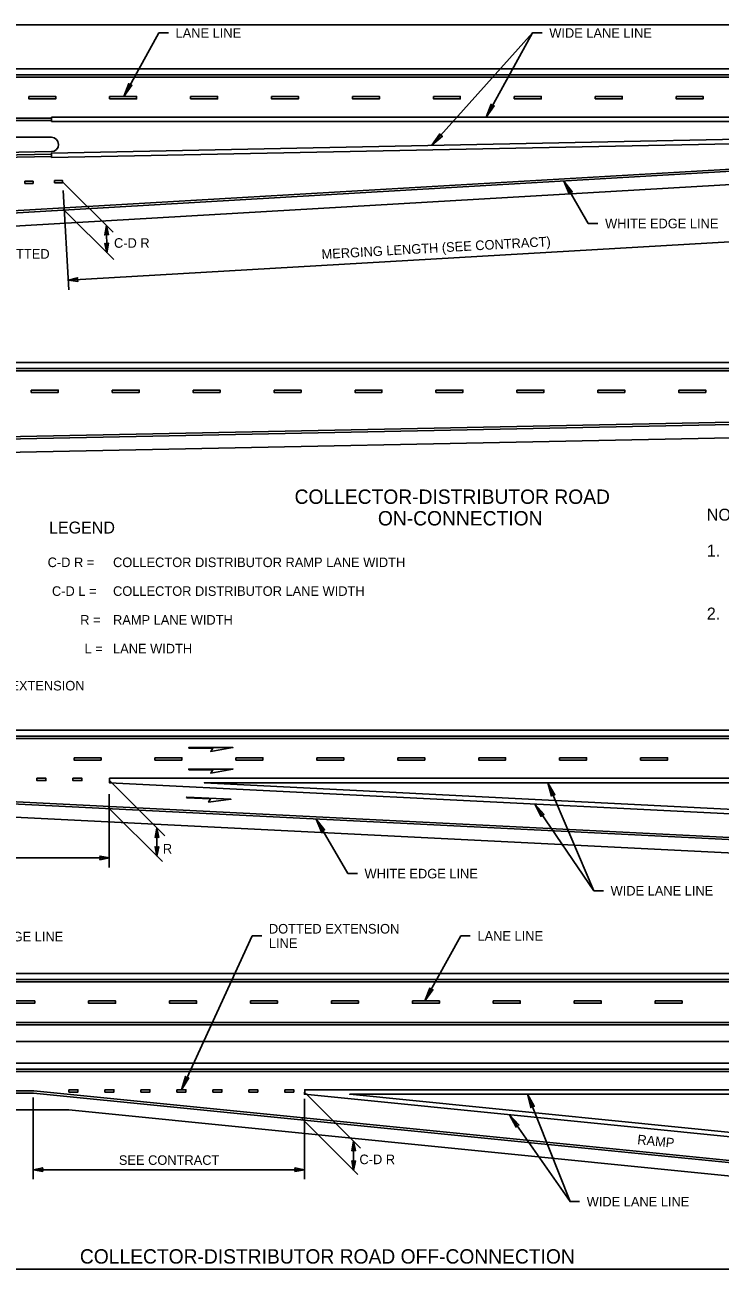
# Model space of a CAD drawing. Extents: x 99862 to 103151, y 100000 to 102076.
# Drawn here: x 100803 to 101963, y 100000 to 102076 of the extents above; entities that cross this region are included whole.
import ezdxf

# ---------------------------------------------------------------- set-up
doc = ezdxf.new("R2010")
doc.units = 0
for name, color, linetype in [('Level 1', 7, 'Continuous'), ('Level 15', 7, 'Continuous'), ('Level 2', 7, 'Continuous'), ('Level 20', 7, 'Continuous'), ('Level 3', 7, 'Continuous'), ('Level 4', 7, 'Continuous'), ('Level 5', 7, 'Continuous'), ('Level 7', 7, 'Continuous')]:
    doc.layers.add(name, color=color, linetype=linetype)

msp = doc.modelspace()

# ---------------------------------------------------------------- linework, layer by layer
at = {"layer": 'Level 1'}
msp.add_lwpolyline([(99862, 99999.5), (103151, 99999.5), (103151, 102075.5), (99862, 102075.5)], close=True, dxfattribs=at)
at = {"layer": 'Level 15'}
for p, q in [((100968.3, 101956.1), (101026.7, 102062)), ((101026.7, 102062), (101042.7, 102062)), ((101026.7, 102062), (101042.7, 102062)), ((101650.1, 102062), (101482.3, 101874.6)), ((101650.1, 102062), (101482.3, 101874.6)), ((101572.7, 101921.7), (101650.1, 102062)), ((101572.7, 101921.7), (101650.1, 102062)), ((101650.1, 102062), (101666.1, 102062)), ((101650.1, 102062), (101666.1, 102062)), ((100866.3, 101813.9), (100950.6, 101729.6)), ((101702.3, 101815), (101743.2, 101744.1)), ((101702.3, 101815), (101743.2, 101744.1)), ((100867.1, 101799.4), (100876.7, 101633.7)), ((100867.2, 101768.3), (100951.5, 101684.1)), ((100940.2, 101695.4), (100939.3, 101740.9)), ((100940.2, 101695.4), (100939.3, 101740.9)), ((101743.2, 101744.1), (101759.2, 101744.1)), ((101743.2, 101744.1), (101759.2, 101744.1)), ((100944.4, 100814.7), (101036.5, 100722.7)), ((100944.4, 100814.7), (101036.5, 100722.7)), ((101675.7, 100810.9), (101752.4, 100630.8)), ((100944.1, 100669.6), (100944.1, 100792.2)), ((100942.3, 100769.9), (101032.7, 100679.4)), ((100942.3, 100769.9), (101032.7, 100679.4)), ((101654.1, 100775.5), (101752.4, 100630.8)), ((101341.9, 100659.4), (101289.3, 100750.5)), ((101341.9, 100659.4), (101289.3, 100750.5)), ((101023.6, 100688.5), (101023.6, 100735.5)), ((100944.2, 100685.6), (100043.2, 100685.6)), ((101341.9, 100659.4), (101357.9, 100659.4)), ((101341.9, 100659.4), (101357.9, 100659.4)), ((101752.4, 100630.8), (101768.4, 100630.8)), ((101752.4, 100630.8), (101768.4, 100630.8)), ((101064.4, 100298.9), (101182.4, 100555.4)), ((101182.4, 100555.4), (101198.4, 100555.4)), ((101182.4, 100555.4), (101198.4, 100555.4)), ((101470.5, 100447), (101530.3, 100555.4)), ((101470.5, 100447), (101530.3, 100555.4)), ((101530.3, 100555.4), (101546.3, 100555.4)), ((101269.9, 100294.7), (101363, 100201.5)), ((100817.4, 100149.4), (100817.4, 100285.7)), ((101269.5, 100149.4), (101269.5, 100283.5)), ((101641.7, 100291.3), (101712.8, 100112.1)), ((101265.4, 100250.6), (101358.8, 100157.2)), ((101612, 100257.1), (101712.8, 100112.1)), ((101351.7, 100212.8), (101351.7, 100177.1)), ((101351.7, 100212.8), (101351.7, 100164.3)), ((101269.5, 100165.4), (100817.5, 100165.4)), ((101712.5, 100112.1), (101728.5, 100112.1)), ((101712.5, 100112.1), (101728.5, 100112.1))]:
    msp.add_line(p, q, dxfattribs=at)
for points in [[(100968.3, 101956.1), (100976.7, 101977.5), (100978.8, 101975.2), (100981.9, 101974.7)], [(100968.3, 101956.1), (100976.7, 101977.5), (100978.8, 101975.2), (100981.9, 101974.7)], [(101572.7, 101921.7), (101581.1, 101943.2), (101583.2, 101940.8), (101586.4, 101940.3)], [(101572.7, 101921.7), (101581.1, 101943.2), (101583.2, 101940.8), (101586.4, 101940.3)], [(101482.3, 101874.6), (101495.3, 101893.6), (101496.8, 101890.8), (101499.8, 101889.6)], [(101482.3, 101874.6), (101495.3, 101893.6), (101496.8, 101890.8), (101499.8, 101889.6)], [(101702.3, 101815), (101716.3, 101796.7), (101713.1, 101796.1), (101711.1, 101793.7)], [(101702.3, 101815), (101716.3, 101796.7), (101713.1, 101796.1), (101711.1, 101793.7)], [(100939.3, 101740.9), (100942.7, 101725.3), (100939.6, 101725.9), (100936.5, 101725.2)], [(100939.3, 101740.9), (100942.7, 101725.3), (100939.6, 101725.9), (100936.5, 101725.2)], [(100940.2, 101695.4), (100942.9, 101711.2), (100939.9, 101710.4), (100936.8, 101711)], [(100940.2, 101695.4), (100942.9, 101711.2), (100939.9, 101710.4), (100936.8, 101711)], [(100875.8, 101649.7), (100891.3, 101653.7), (100890.8, 101650.6), (100891.7, 101647.5)], [(100875.8, 101649.7), (100891.3, 101653.7), (100890.8, 101650.6), (100891.7, 101647.5)], [(101675.7, 100810.9), (101687.4, 100791.1), (101684.2, 100790.9), (101681.9, 100788.8)], [(101654.1, 100775.5), (101669.4, 100758.2), (101666.4, 100757.4), (101664.5, 100754.9)], [(101289.3, 100750.5), (101298.1, 100729.3), (101300.2, 100731.7), (101303.3, 100732.3)], [(101289.3, 100750.5), (101298.1, 100729.3), (101300.2, 100731.7), (101303.3, 100732.3)], [(101023.6, 100735.5), (101026.7, 100719.8), (101023.6, 100720.5), (101020.5, 100719.8)], [(100944.2, 100685.6), (100928.4, 100682.5), (100929.2, 100685.6), (100928.4, 100688.7)], [(101023.6, 100688.5), (101026.7, 100704.3), (101023.6, 100703.5), (101020.5, 100704.2)], [(101470.5, 100447), (101478.9, 100468.5), (101481, 100466.1), (101484.1, 100465.6)], [(101470.5, 100447), (101478.9, 100468.5), (101481, 100466.1), (101484.1, 100465.6)], [(101064.4, 100298.9), (101071.2, 100320.9), (101073.5, 100318.7), (101076.6, 100318.4)], [(101641.7, 100291.3), (101647.3, 100269), (101649.7, 100271), (101652.9, 100271.2)], [(101641.7, 100291.3), (101647.3, 100269), (101649.7, 100271), (101652.9, 100271.2)], [(101612, 100257.1), (101622.6, 100236.6), (101624.4, 100239.2), (101627.5, 100240)], [(101612, 100257.1), (101622.6, 100236.6), (101624.4, 100239.2), (101627.5, 100240)], [(101351.7, 100212.8), (101354.8, 100197.1), (101351.7, 100197.8), (101348.6, 100197.1)], [(100817.5, 100165.4), (100833.2, 100162.4), (100832.4, 100165.4), (100833.2, 100168.5)], [(100817.5, 100165.4), (100833.2, 100162.4), (100832.4, 100165.4), (100833.2, 100168.5)], [(101269.5, 100165.4), (101253.8, 100162.4), (101254.5, 100165.4), (101253.8, 100168.5)], [(101269.5, 100165.4), (101253.8, 100162.4), (101254.5, 100165.4), (101253.8, 100168.5)], [(101351.7, 100164.3), (101354.8, 100180), (101351.7, 100179.3), (101348.6, 100180)]]:
    msp.add_lwpolyline(points, close=True, dxfattribs=at)
msp.add_lwpolyline([(102055.8, 101718.2), (100875.8, 101649.7)], dxfattribs=at)
at = {"layer": 'Level 2'}
for p, q in [((103122.6, 102002), (99944, 102002)), ((99944, 101888), (100847.5, 101888)), ((100476.9, 101721.6), (102047.6, 101812.9)), ((99911.9, 101512.1), (103093.2, 101512.1)), ((99944, 100898.7), (102630.3, 100898.7)), ((100224.7, 100493), (102409.4, 100493)), ((102409.4, 100379), (100224.7, 100379)), ((100224.7, 100343), (102409.4, 100343))]:
    msp.add_line(p, q, dxfattribs=at)
for points in [[(100847.7, 101864), (100247.6, 101852), (99944, 101852)], [(103091.7, 101403.9), (102836.7, 101403.9), (99911.9, 101344.9)], [(102630.3, 100670.7), (102442.8, 100670.7), (100162.8, 100784.7), (99944, 100784.7)], [(102630.3, 100670.7), (102442.8, 100670.7), (100162.8, 100784.7), (99944, 100784.7)], [(100224.7, 100265), (100876.6, 100265), (102275.7, 100125.1)]]:
    msp.add_lwpolyline(points, dxfattribs=at)
msp.add_arc((100847.5, 101876), 12, 271.1458, 90, dxfattribs=at)
at = {"layer": 'Level 3'}
for p, q in [((103122.6, 101991.9), (99944, 101991.9)), ((103122.6, 101991.9), (99944, 101991.9)), ((99944, 101988.1), (103122.6, 101988.1)), ((100847.9, 101914.2), (100847.9, 101921.7)), ((100847.9, 101914.2), (100847.9, 101921.7)), ((100847.9, 101921.7), (102922.5, 101921.7)), ((100847.9, 101921.7), (102922.5, 101921.7)), ((100847.9, 101914.2), (102922.5, 101914.2)), ((100847.9, 101914.2), (102922.5, 101914.2)), ((99911.9, 101501.9), (103093.2, 101501.9)), ((103093.2, 101498.2), (99911.9, 101498.2)), ((102630.4, 100888.6), (99944, 100888.6)), ((99944, 100884.8), (102630.4, 100884.8)), ((100224.7, 100482.9), (102409.4, 100482.9)), ((102409.4, 100479.1), (100224.7, 100479.1)), ((100224.7, 100332.9), (102409.4, 100332.9)), ((102409.4, 100329.2), (100224.7, 100329.2))]:
    msp.add_line(p, q, dxfattribs=at)
for points in [[(100847.9, 101854.2), (100847.8, 101861.7), (102922.5, 101903.7), (102922.7, 101896.2)], [(100847.9, 101854.2), (100847.8, 101861.7), (102922.5, 101903.7), (102922.7, 101896.2)], [(102504.5, 100810.9), (102504.5, 100818.4), (100944.5, 100818.4), (100944.3, 100811), (102504.3, 100733), (102504.7, 100740.4), (101102.5, 100810.9)], [(102109, 100214.9), (102108.2, 100207.4), (101269.7, 100291.3), (101270.1, 100298.8), (102111.6, 100298.8), (102111.6, 100291.3), (101345.3, 100291.3)]]:
    msp.add_lwpolyline(points, close=True, dxfattribs=at)
msp.add_lwpolyline([(99944, 101844.1), (100247.6, 101844.1), (100847.9, 101856.1), (100847.8, 101859.9), (100247.5, 101847.9), (99944, 101847.9)], dxfattribs=at)
at = {"layer": 'Level 4'}
for p, q in [((100847.9, 101919.9), (99944, 101919.9)), ((99944, 101916.1), (100847.9, 101916.1)), ((100224.7, 100410.9), (102409.4, 100410.9)), ((102409.4, 100407.2), (100224.7, 100407.2))]:
    msp.add_line(p, q, dxfattribs=at)
for points in [[(100809.7, 101956.1), (100854.7, 101956.1), (100854.7, 101952.1), (100809.7, 101952.2)], [(100944.7, 101956.1), (100989.7, 101956.1), (100989.7, 101952.1), (100944.7, 101952.2)], [(101079.7, 101956.1), (101124.7, 101956.1), (101124.7, 101952.1), (101079.7, 101952.2)], [(101214.7, 101956.1), (101259.7, 101956.1), (101259.7, 101952.1), (101214.7, 101952.2)], [(101214.7, 101956.1), (101259.7, 101956.1), (101259.7, 101952.1), (101214.7, 101952.2)], [(101349.7, 101956.1), (101394.7, 101956.1), (101394.7, 101952.1), (101349.7, 101952.2)], [(101349.7, 101956.1), (101394.7, 101956.1), (101394.7, 101952.1), (101349.7, 101952.2)], [(101484.7, 101956.1), (101529.7, 101956.1), (101529.7, 101952.1), (101484.7, 101952.2)], [(101484.7, 101956.1), (101529.7, 101956.1), (101529.7, 101952.1), (101484.7, 101952.2)], [(101619.7, 101956.1), (101664.7, 101956.1), (101664.7, 101952.1), (101619.7, 101952.2)], [(101754.7, 101956.1), (101799.7, 101956.1), (101799.7, 101952.1), (101754.7, 101952.2)], [(101889.7, 101956.1), (101934.7, 101956.1), (101934.7, 101952.1), (101889.7, 101952.2)], [(100803.4, 101810.9), (100816.9, 101810.9), (100816.9, 101814.7), (100803.4, 101814.7)], [(100803.4, 101810.9), (100816.9, 101810.9), (100816.9, 101814.7), (100803.4, 101814.7)], [(100852.8, 101812), (100866.3, 101812), (100866.3, 101815.7), (100852.8, 101815.7)], [(100852.8, 101812), (100866.3, 101812), (100866.3, 101815.7), (100852.8, 101815.7)], [(100814, 101466.2), (100859, 101466.2), (100859, 101462.2), (100814, 101462.2)], [(100949, 101466.2), (100994, 101466.2), (100994, 101462.2), (100949, 101462.2)], [(101084, 101466.2), (101129, 101466.2), (101129, 101462.2), (101084, 101462.2)], [(101219, 101466.2), (101264, 101466.2), (101264, 101462.2), (101219, 101462.2)], [(101354, 101466.2), (101399, 101466.2), (101399, 101462.2), (101354, 101462.2)], [(101489, 101466.2), (101534, 101466.2), (101534, 101462.2), (101489, 101462.2)], [(101624, 101466.2), (101669, 101466.2), (101669, 101462.2), (101624, 101462.2)], [(101759, 101466.2), (101804, 101466.2), (101804, 101462.2), (101759, 101462.2)], [(101894, 101466.2), (101939, 101466.2), (101939, 101462.2), (101894, 101462.2)], [(100885.3, 100852.7), (100930.3, 100852.7), (100930.3, 100848.7), (100885.3, 100848.7)], [(101020.3, 100852.7), (101065.3, 100852.7), (101065.3, 100848.7), (101020.3, 100848.7)], [(101020.3, 100852.7), (101065.3, 100852.7), (101065.3, 100848.7), (101020.3, 100848.7)], [(101155.3, 100852.7), (101200.3, 100852.7), (101200.3, 100848.7), (101155.3, 100848.7)], [(101290.3, 100852.7), (101335.3, 100852.7), (101335.3, 100848.7), (101290.3, 100848.7)], [(101425.3, 100852.7), (101470.3, 100852.7), (101470.3, 100848.7), (101425.3, 100848.7)], [(101560.3, 100852.7), (101605.3, 100852.7), (101605.3, 100848.7), (101560.3, 100848.7)], [(101695.3, 100852.7), (101740.3, 100852.7), (101740.3, 100848.7), (101695.3, 100848.7)], [(101830.3, 100852.7), (101875.3, 100852.7), (101875.3, 100848.7), (101830.3, 100848.7)], [(101830.3, 100852.7), (101875.3, 100852.7), (101875.3, 100848.7), (101830.3, 100848.7)], [(100823.4, 100818.6), (100838.4, 100818.6), (100838.4, 100814.6), (100823.4, 100814.6)], [(100823.4, 100818.6), (100838.4, 100818.6), (100838.4, 100814.6), (100823.4, 100814.6)], [(100883.4, 100818.6), (100898.4, 100818.6), (100898.4, 100814.6), (100883.4, 100814.6)], [(100883.4, 100818.6), (100898.4, 100818.6), (100898.4, 100814.6), (100883.4, 100814.6)], [(100774.7, 100447), (100819.7, 100447), (100819.7, 100443), (100774.7, 100443)], [(100774.7, 100447), (100819.7, 100447), (100819.7, 100443), (100774.7, 100443)], [(100909.7, 100447), (100954.7, 100447), (100954.7, 100443), (100909.7, 100443)], [(100909.7, 100447), (100954.7, 100447), (100954.7, 100443), (100909.7, 100443)], [(101044.7, 100447), (101089.7, 100447), (101089.7, 100443), (101044.7, 100443)], [(101044.7, 100447), (101089.7, 100447), (101089.7, 100443), (101044.7, 100443)], [(101179.7, 100447), (101224.7, 100447), (101224.7, 100443), (101179.7, 100443)], [(101179.7, 100447), (101224.7, 100447), (101224.7, 100443), (101179.7, 100443)], [(101314.7, 100447), (101359.7, 100447), (101359.7, 100443), (101314.7, 100443)], [(101314.7, 100447), (101359.7, 100447), (101359.7, 100443), (101314.7, 100443)], [(101449.7, 100447), (101494.7, 100447), (101494.7, 100443), (101449.7, 100443)], [(101449.7, 100447), (101494.7, 100447), (101494.7, 100443), (101449.7, 100443)], [(101584.7, 100447), (101629.7, 100447), (101629.7, 100443), (101584.7, 100443)], [(101584.7, 100447), (101629.7, 100447), (101629.7, 100443), (101584.7, 100443)], [(101719.7, 100447), (101764.7, 100447), (101764.7, 100443), (101719.7, 100443)], [(101719.7, 100447), (101764.7, 100447), (101764.7, 100443), (101719.7, 100443)], [(101854.7, 100447), (101899.7, 100447), (101899.7, 100443), (101854.7, 100443)], [(101854.7, 100447), (101899.7, 100447), (101899.7, 100443), (101854.7, 100443)], [(100876.9, 100298.9), (100891.9, 100298.9), (100891.9, 100294.9), (100876.9, 100294.9)], [(100936.9, 100298.9), (100951.9, 100298.9), (100951.9, 100294.9), (100936.9, 100294.9)], [(100996.9, 100298.9), (101011.9, 100298.9), (101011.9, 100294.9), (100996.9, 100294.9)], [(101056.9, 100298.9), (101071.9, 100298.9), (101071.9, 100294.9), (101056.9, 100294.9)], [(101116.9, 100298.9), (101131.9, 100298.9), (101131.9, 100294.9), (101116.9, 100294.9)], [(101176.9, 100298.9), (101191.9, 100298.9), (101191.9, 100294.9), (101176.9, 100294.9)], [(101236.9, 100298.9), (101251.9, 100298.9), (101251.9, 100294.9), (101236.9, 100294.9)]]:
    msp.add_lwpolyline(points, close=True, dxfattribs=at)
for points in [[(100475.1, 101747.4), (102048.8, 101838.9), (103122.6, 101860.8)], [(103122.6, 101857.1), (102049, 101835.1), (100475.5, 101743.7)], [(103093.2, 101429.9), (102838.2, 101429.9), (99911.9, 101370.9)], [(99944, 100816.6), (100043.4, 100816.6), (102323.5, 100702.6), (102630.3, 100702.6)], [(102630.3, 100698.8), (102323.3, 100698.8), (100043.4, 100812.8), (99944, 100812.8)], [(100224.7, 100296.9), (100818, 100296.9), (102278.3, 100150.9)], [(102277.9, 100147.1), (100817.6, 100293.2), (100224.7, 100293.2)]]:
    msp.add_lwpolyline(points, dxfattribs=at)
at = {"layer": 'Level 5'}
for points in [[(101076.6, 100868.7), (101116.7, 100868.7), (101113.5, 100863.3), (101150.4, 100869.8), (101076.6, 100869.8)], [(101076.6, 100832.6), (101116.7, 100832.6), (101113.5, 100827.2), (101150.4, 100833.7), (101076.6, 100833.7)], [(101073.1, 100786.1), (101113.2, 100784.1), (101109.7, 100778.8), (101146.9, 100783.5), (101073.2, 100787.1)]]:
    msp.add_lwpolyline(points, close=True, dxfattribs=at)
at = {"layer": 'Level 7'}
msp.add_lwpolyline([(99911.9, 101367.2), (102838.2, 101426.2), (103093.2, 101426.2)], dxfattribs=at)

# ---------------------------------------------------------------- texts
at = {"layer": 'Level 20'}
for s, height, p in [('LANE LINE', 16, (101054.7, 102054)), ('WIDE LANE LINE', 16, (101678.1, 102054)), ('WHITE EDGE LINE', 16, (101771.2, 101736.1)), ('C-D R', 16, (100952, 101703.6)), ('C-D R', 16, (100952, 101703.6)), ('WIDE DOTTED', 16, (100694.8, 101685.4)), ('COLLECTOR-DISTRIBUTOR ROAD', 24, (101253.2, 101276.3)), ('NOTES', 20, (101940.9, 101248.3)), ('LEGEND', 20, (100843.6, 101226.8)), ('ON-CONNECTION', 24, (101392.2, 101240.3)), ('1.', 20, (101940.9, 101188.3)), ('1.', 20, (101940.9, 101188.3)), ('C-D R =', 16, (100841.3, 101170.8)), ('C-D R =', 16, (100841.3, 101170.8)), ('COLLECTOR DISTRIBUTOR RAMP LANE WIDTH', 16, (100950.4, 101170.8)), ('C-D L =', 16, (100848.5, 101122.8)), ('C-D L =', 16, (100848.5, 101122.8)), ('COLLECTOR DISTRIBUTOR LANE WIDTH', 16, (100950.4, 101122.8)), ('2.', 20, (101940.9, 101083.3)), ('2.', 20, (101940.9, 101083.3)), ('R =', 16, (100895.6, 101074.8)), ('R =', 16, (100895.6, 101074.8)), ('RAMP LANE WIDTH', 16, (100950.4, 101074.8)), ('L =', 16, (100902.9, 101026.8)), ('L =', 16, (100902.9, 101026.8)), ('LANE WIDTH', 16, (100950.4, 101026.8)), ('DOTTED EXTENSION', 16, (100685.3, 100965)), ('R', 16, (101033.5, 100692.9)), ('R', 16, (101033.5, 100692.9)), ('WHITE EDGE LINE', 16, (101369.9, 100651.4)), ('WIDE LANE LINE', 16, (101780.4, 100622.8)), ('YELLOW EDGE LINE', 16, (100658.1, 100546.3)), ('DOTTED EXTENSION', 16, (101210.4, 100559.4)), ('LANE LINE', 16, (101558.3, 100547.4)), ('LINE', 16, (101210.4, 100535.4)), ('SEE CONTRACT', 16, (100960.1, 100173.4)), ('C-D R', 16, (101361.4, 100174.6)), ('COLLECTOR-DISTRIBUTOR ROAD OFF-CONNECTION', 24, (100895.1, 100008.7))]:
    msp.add_text(s, height=height, dxfattribs=at).set_placement(p)
for s, rotation, p in [('MERGING LENGTH (SEE CONTRACT)', 3.2543, (101298.7, 101684.7)), ('RAMP', 354.3427, (101824.4, 100208)), ('WIDE LANE LINE', 360, (101740.5, 100104.1))]:
    msp.add_text(s, height=16, rotation=rotation, dxfattribs=at).set_placement(p)

doc.saveas('drawing.dxf')
